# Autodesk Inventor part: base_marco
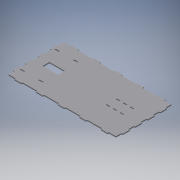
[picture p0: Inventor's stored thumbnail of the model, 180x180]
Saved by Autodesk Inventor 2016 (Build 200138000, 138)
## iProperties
Created: 2017-06
Part Number: base_marco
Material: Generic
Document SubType Name: Modeling
Designer: laboratorioesan
Density: 1 g/cm^3
Appearance: Default
Author: laboratorioesan
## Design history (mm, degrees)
sketch "Sketch1"
  geometry: L1 (312.5, 0)-(412.5, 0) reference; L2 (312.5, 0)-(312.5, -18.5) reference; L3 (412.5, -18.5)-(312.5, -18.5) reference; L4 (412.5, 0)-(412.5, -18.5) reference; L5 (0, 0)-(100, 0) reference; L6 (0, 0)-(0, -18.5) reference; L7 (100, -18.5)-(0, -18.5) reference; L8 (100, 0)-(100, -18.5) reference; L9 (512.5, 80)-(512.5, 180) reference; L10 (512.5, 80)-(531, 80) reference; L11 (531, 180)-(531, 80) reference; L12 (512.5, 180)-(531, 180) reference; L13 (512.5, 620)-(512.5, 720) reference; L14 (512.5, 620)-(531, 620) reference; L15 (531, 720)-(531, 620) reference; L16 (512.5, 720)-(531, 720) reference; L17 (512.5, 440)-(512.5, 540) reference; L18 (512.5, 440)-(531, 440) reference; L19 (531, 540)-(531, 440) reference; L20 (512.5, 540)-(531, 540) reference; L21 (512.5, 260)-(512.5, 360) reference; L22 (512.5, 260)-(531, 260) reference; L23 (531, 360)-(531, 260) reference; L24 (512.5, 360)-(531, 360) reference; L25 (312.5, 818.5)-(412.5, 818.5) reference; L26 (312.5, 818.5)-(312.5, 800) reference; L27 (412.5, 800)-(312.5, 800) reference; L28 (412.5, 818.5)-(412.5, 800) reference; L29 (0, 818.5)-(100, 818.5) reference; L30 (0, 818.5)-(0, 800) reference; L31 (100, 800)-(0, 800) reference; L32 (100, 818.5)-(100, 800) reference; L33 (-312.5, 818.5)-(-212.5, 818.5) reference; L34 (-312.5, 818.5)-(-312.5, 800) reference; L35 (-212.5, 800)-(-312.5, 800) reference; L36 (-212.5, 818.5)-(-212.5, 800) reference; L37 (-625, 818.5)-(-525, 818.5) reference; L38 (-625, 818.5)-(-625, 800) reference; L39 (-525, 800)-(-625, 800) reference; L40 (-525, 818.5)-(-525, 800) reference; L41 (-937.5, 818.5)-(-837.5, 818.5) reference; L42 (-937.5, 818.5)-(-937.5, 800) reference; L43 (-837.5, 800)-(-937.5, 800) reference; L44 (-837.5, 818.5)-(-837.5, 800) reference; L45 (-1037.5, 720)-(-1037.5, 620) reference; L46 (-1037.5, 720)-(-1056, 720) reference; L47 (-1056, 620)-(-1056, 720) reference; L48 (-1037.5, 620)-(-1056, 620) reference; L49 (-1037.5, 540)-(-1037.5, 440) reference; L50 (-1037.5, 540)-(-1056, 540) reference; L51 (-1056, 440)-(-1056, 540) reference; L52 (-1037.5, 440)-(-1056, 440) reference; L53 (-1037.5, 360)-(-1037.5, 260) reference; L54 (-1037.5, 360)-(-1056, 360) reference; L55 (-1056, 260)-(-1056, 360) reference; L56 (-1037.5, 260)-(-1056, 260) reference; L57 (-1037.5, 180)-(-1037.5, 80) reference; L58 (-1037.5, 180)-(-1056, 180) reference; L59 (-1056, 80)-(-1056, 180) reference; L60 (-1037.5, 80)-(-1056, 80) reference; L61 (-937.5, 0)-(-837.5, 0) reference; L62 (-937.5, 0)-(-937.5, -18.5) reference; L63 (-837.5, -18.5)-(-937.5, -18.5) reference; L64 (-837.5, 0)-(-837.5, -18.5) reference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; 2 further points; 1 other entity
  constraints: 152 end point, 38 parallel, 19 horizontal, 19 perpendicular, 18 point on line, 1 other
  dimensions: "d0" = 18 distance of L81.end L80.end; "d1" = 18 distance of L85.end L84.end; "d2" = 18 distance of L89.end L88.end; "d3" = 18 distance of L93.end L92.end; "d4" = 18 distance of L97.end L96.end; "d5" = 18 distance of L101.end L102.end; "d6" = 18 distance of L105.end L106.end; "d7" = 18 distance of L109.end L110.end; "d8" = 18 distance of L113.end L114.end; "d9" = 18 distance of L117.end L116.end; "d10" = 18 distance of L121.end L120.end; "d11" = 18 distance of L125.end L124.end; "d12" = 18 distance of L128.end L129.end; "d13" = 18 distance of L133.end L132.end; "d14" = 18 distance of L137.end L138.end; "d15" = 18 distance of L141.end L142.end; "d16" = 18 distance of L145.end L146.end; "d17" = 18 distance of L149.end L150.end
extrude "Extrusion1" new body sketch "Sketch1" distance "d18" = 15.5; taper "d19" = 0 deg
extrude "Extrusion2" cut sketch "Sketch2" distance "d29" = 15.5; taper "d30" = 0 deg
sketch "Sketch3"
  geometry: L1 (45.342, 320)-(45.342, 335.5) reference; L2 (45.342, 335.5)-(95.342, 335.5) reference; L3 (95.342, 335.5)-(95.342, 320) reference; L4 (95.342, 320)-(45.342, 320) reference; L5 (195.342, 480)-(195.342, 464.5) reference; L6 (195.342, 464.5)-(145.342, 464.5) reference; L7 (145.342, 464.5)-(145.342, 480) reference; L8 (145.342, 480)-(195.342, 480) reference; L9 (145.342, 335.5)-(195.342, 335.5) reference; L10 (195.342, 335.5)-(195.342, 320) reference; L11 (195.342, 320)-(145.342, 320) reference; L12 (145.342, 320)-(145.342, 335.5) reference; L13 (95.342, 480)-(95.342, 464.5) reference; L14 (95.342, 464.5)-(45.342, 464.5) reference; L15 (45.342, 464.5)-(45.342, 480) reference; L16 (45.342, 480)-(95.342, 480) reference; L17 (295.348, 480)-(295.348, 464.5) reference; L18 (295.348, 464.5)-(245.348, 464.5) reference; L19 (245.348, 464.5)-(245.348, 480) reference; L20 (245.348, 480)-(295.348, 480) reference; L21 (245.348, 320)-(245.348, 335.5) reference; L22 (245.348, 335.5)-(295.348, 335.5) reference; L23 (295.348, 335.5)-(295.348, 320) reference; L24 (295.348, 320)-(245.348, 320) reference; L25 (512.5, 0)-(512.5, 80) reference; L26 (512.5, 80)-(530.5, 80) reference; L27 (530.5, 80)-(530.5, 180) reference; L28 (530.5, 180)-(512.5, 180) reference; L29 (512.5, 180)-(512.5, 260) reference; L30 (512.5, 260)-(530.5, 260) reference; L31 (530.5, 260)-(530.5, 360) reference; L32 (530.5, 360)-(512.5, 360) reference; L33 (512.5, 360)-(512.5, 440) reference; L34 (512.5, 440)-(530.5, 440) reference; L35 (530.5, 440)-(530.5, 540) reference; L36 (530.5, 540)-(512.5, 540) reference; L37 (512.5, 540)-(512.5, 620) reference; L38 (512.5, 620)-(530.5, 620) reference; L39 (530.5, 620)-(530.5, 720) reference; L40 (530.5, 720)-(512.5, 720) reference; L41 (512.5, 720)-(512.5, 800) reference; L42 (512.5, 800)-(412.5, 800) reference; L43 (412.5, 800)-(412.5, 818) reference; L44 (412.5, 818)-(312.5, 818) reference; L45 (312.5, 818)-(312.5, 800) reference; L46 (312.5, 800)-(100, 800) reference; L47 (100, 800)-(100, 818) reference; L48 (100, 818)-(0, 818) reference; L49 (0, 818)-(0, 800) reference; L50 (0, 800)-(-212.5, 800) reference; L51 (-212.5, 800)-(-212.5, 818) reference; L52 (-212.5, 818)-(-312.5, 818) reference; L53 (-312.5, 818)-(-312.5, 800) reference; L54 (-312.5, 800)-(-525, 800) reference; L55 (-525, 800)-(-525, 818) reference; L56 (-525, 818)-(-625, 818) reference; L57 (-625, 818)-(-625, 800) reference; L58 (-625, 800)-(-837.5, 800) reference; L59 (-837.5, 800)-(-837.5, 818) reference; L60 (-837.5, 818)-(-937.5, 818) reference; L61 (-937.5, 818)-(-937.5, 800) reference; L62 (-937.5, 800)-(-1037.5, 800) reference; L63 (-1037.5, 800)-(-1037.5, 720) reference; L64 (-1037.5, 720)-(-1055.5, 720) reference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; 5 further points
  constraints: 10 end point, 6 midpoint, 2 parallel, 1 horizontal, 1 horizontal alignment, 1 perpendicular, 1 vertical alignment
  dimensions: "d31" = 220 distance of L106.end L107.end; "d32" = 100 distance of L105.end L106.end
extrude "Extrusion3" cut sketch "Sketch3" distance "d34" = 18.5; taper "d35" = 0 deg
sketch "Sketch4"
  geometry: L1 (-677.5, 450)-(-677.5, 350) reference; L2 (-677.5, 350)-(-897.5, 350) reference; L3 (-897.5, 350)-(-897.5, 450) reference; L4 (-897.5, 450)-(-677.5, 450) reference; L5 (45.342, 320)-(45.342, 335.5) reference; L6 (45.342, 335.5)-(95.342, 335.5) reference; L7 (95.342, 335.5)-(95.342, 320) reference; L8 (95.342, 320)-(45.342, 320) reference; L9 (195.342, 480)-(195.342, 464.5) reference; L10 (195.342, 464.5)-(145.342, 464.5) reference; L11 (145.342, 464.5)-(145.342, 480) reference; L12 (145.342, 480)-(195.342, 480) reference; L13 (145.342, 335.5)-(195.342, 335.5) reference; L14 (195.342, 335.5)-(195.342, 320) reference; L15 (195.342, 320)-(145.342, 320) reference; L16 (145.342, 320)-(145.342, 335.5) reference; L17 (95.342, 480)-(95.342, 464.5) reference; L18 (95.342, 464.5)-(45.342, 464.5) reference; L19 (45.342, 464.5)-(45.342, 480) reference; L20 (45.342, 480)-(95.342, 480) reference; L21 (295.348, 480)-(295.348, 464.5) reference; L22 (295.348, 464.5)-(245.348, 464.5) reference; L23 (245.348, 464.5)-(245.348, 480) reference; L24 (245.348, 480)-(295.348, 480) reference; L25 (245.348, 320)-(245.348, 335.5) reference; L26 (245.348, 335.5)-(295.348, 335.5) reference; L27 (295.348, 335.5)-(295.348, 320) reference; L28 (295.348, 320)-(245.348, 320) reference; L29 (512.5, 0)-(512.5, 80) reference; L30 (512.5, 80)-(530.5, 80) reference; L31 (530.5, 80)-(530.5, 180) reference; L32 (530.5, 180)-(512.5, 180) reference; L33 (512.5, 180)-(512.5, 260) reference; L34 (512.5, 260)-(530.5, 260) reference; L35 (530.5, 260)-(530.5, 360) reference; L36 (530.5, 360)-(512.5, 360) reference; L37 (512.5, 360)-(512.5, 440) reference; L38 (512.5, 440)-(530.5, 440) reference; L39 (530.5, 440)-(530.5, 540) reference; L40 (530.5, 540)-(512.5, 540) reference; L41 (512.5, 540)-(512.5, 620) reference; L42 (512.5, 620)-(530.5, 620) reference; L43 (530.5, 620)-(530.5, 720) reference; L44 (530.5, 720)-(512.5, 720) reference; L45 (512.5, 720)-(512.5, 800) reference; L46 (512.5, 800)-(412.5, 800) reference; L47 (412.5, 800)-(412.5, 818) reference; L48 (412.5, 818)-(312.5, 818) reference; L49 (312.5, 818)-(312.5, 800) reference; L50 (312.5, 800)-(100, 800) reference; L51 (100, 800)-(100, 818) reference; L52 (100, 818)-(0, 818) reference; L53 (0, 818)-(0, 800) reference; L54 (0, 800)-(-212.5, 800) reference; L55 (-212.5, 800)-(-212.5, 818) reference; L56 (-212.5, 818)-(-312.5, 818) reference; L57 (-312.5, 818)-(-312.5, 800) reference; L58 (-312.5, 800)-(-525, 800) reference; L59 (-525, 800)-(-525, 818) reference; L60 (-525, 818)-(-625, 818) reference; L61 (-625, 818)-(-625, 800) reference; L62 (-625, 800)-(-837.5, 800) reference; L63 (-837.5, 800)-(-837.5, 818) reference; L64 (-837.5, 818)-(-937.5, 818) reference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; 1 further point
  constraints: 32 end point, 9 point on line, 8 parallel, 4 horizontal, 4 perpendicular
  dimensions: "d36" = 60 distance of L132.end L133.end; "d37" = 60 distance of L136.end L137.end; "d38" = 60 distance of L141.end L140.end; "d39" = 60 distance of L144.end L145.end; "d40" = 20 horizontal distance of L79.end L139.start
extrude "Extrusion4" cut sketch "Sketch4" distance "d41" = 15.5; taper "d42" = 0 deg
body "Solid1"
node "Reference1"
node "Reference2"
node "Reference3"
node "Reference4"
node "Reference5"
node "Reference6"
node "Reference7"
node "Reference8"
node "Reference9"
node "Reference10"
node "Reference11"
node "Reference12"
node "Reference13"
node "Reference14"
node "Reference15"
node "Reference16"
node "Reference17"
node "Reference18"
node "Reference19"
node "Reference20"
node "Reference21"
node "Reference22"
node "Projected Loop2"
node "Reference29"
node "Reference30"
node "Reference31"
node "Projected Loop3"
node "Reference32"
node "Reference33"
node "Reference34"
node "Reference35"
node "Reference36"
node "Reference37"
node "Reference38"
node "Reference39"
other parameters: "d24" = 15.5
